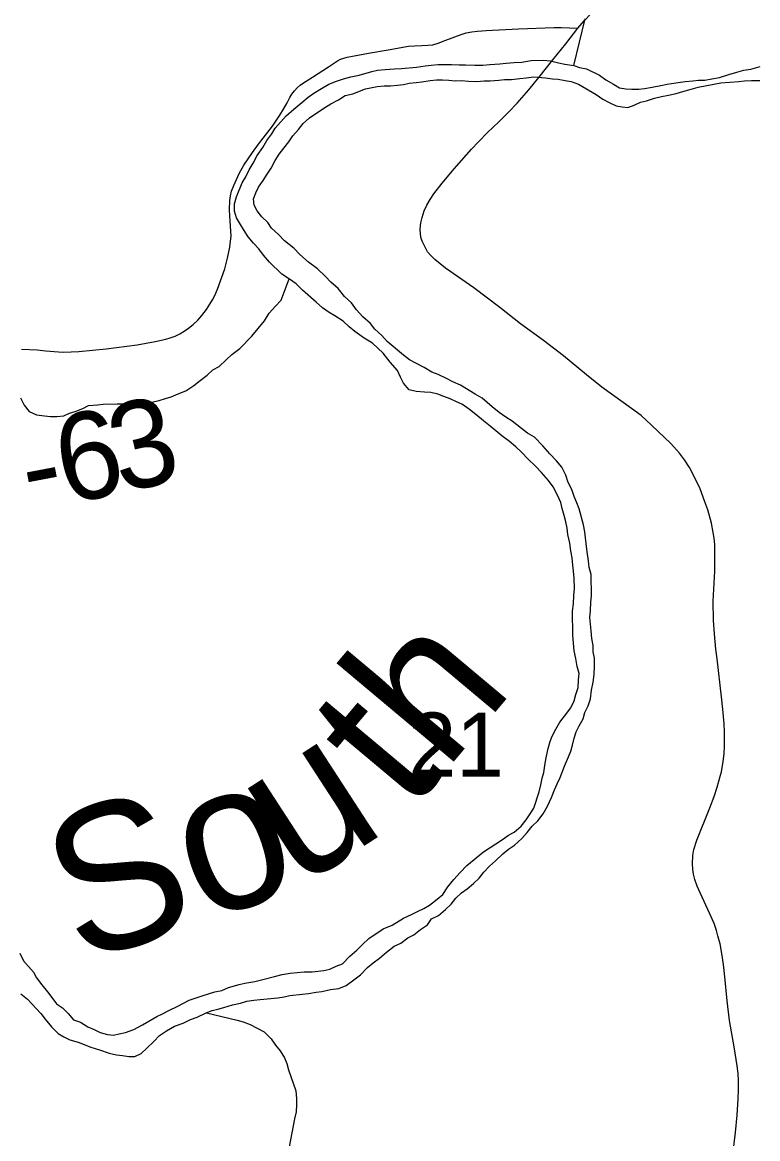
# Model space of a CAD drawing. Extents: x -3.3 to 34, y 0 to 56.8.
# Drawn here: x -2.175 to -1.696, y 29.951 to 30.679 of the extents above; entities that cross this region are included whole.
import ezdxf

# ---------------------------------------------------------------- set-up
doc = ezdxf.new("R2010")
doc.units = 0
for name, color, linetype in [('GM_X_Major_River', 7, 'Continuous'), ('GM_X_Major_River_Text', 7, 'Continuous'), ('GM_X_Section_Text', 7, 'Continuous'), ('GM_X_State_Route', 7, 'Continuous'), ('GM_X_Township_Road', 7, 'Continuous'), ('GM_X_Township_Road_Text', 7, 'Continuous'), ('GT_Project_Soil_Layers', 7, 'Continuous')]:
    doc.layers.add(name, color=color, linetype=linetype)

msp = doc.modelspace()

# ---------------------------------------------------------------- linework, layer by layer
at = {"layer": 'GM_X_Major_River'}
for points in [[(-2.03157, 30.57411), (-2.02934, 30.57794), (-2.02713, 30.58252), (-2.02453, 30.58674), (-2.02195, 30.59171), (-2.01823, 30.59707), (-2.01563, 30.60166), (-2.01228, 30.60588), (-2.01006, 30.6097), (-2.00296, 30.61777), (-1.99809, 30.62202), (-1.99284, 30.62626), (-1.98871, 30.62973), (-1.98496, 30.63244), (-1.98007, 30.63555), (-1.97518, 30.63827), (-1.97027, 30.64024), (-1.96574, 30.64182), (-1.96083, 30.64302), (-1.95554, 30.64424), (-1.94723, 30.64663), (-1.94345, 30.64744), (-1.93852, 30.64789), (-1.93246, 30.64835), (-1.92792, 30.64842), (-1.91807, 30.64931), (-1.91239, 30.65015), (-1.9086, 30.65058), (-1.90406, 30.65103), (-1.89534, 30.65114), (-1.89041, 30.65084), (-1.88624, 30.65089), (-1.88017, 30.6506), (-1.87486, 30.65067), (-1.87032, 30.65111), (-1.86388, 30.65158), (-1.85971, 30.65202), (-1.85441, 30.65247), (-1.84948, 30.65254), (-1.84343, 30.65377), (-1.83547, 30.65388), (-1.83091, 30.65356), (-1.82558, 30.65212), (-1.8214, 30.65142), (-1.8157, 30.65036), (-1.81189, 30.64927), (-1.80733, 30.6482), (-1.79893, 30.64414), (-1.79472, 30.64116), (-1.78975, 30.6382), (-1.78593, 30.63597), (-1.78175, 30.63527), (-1.77795, 30.63495), (-1.77341, 30.63501), (-1.76962, 30.63544), (-1.7647, 30.63627), (-1.75903, 30.63749), (-1.75487, 30.6383), (-1.74919, 30.63914), (-1.74314, 30.63998), (-1.73821, 30.64043), (-1.73443, 30.64087), (-1.73026, 30.64092), (-1.72572, 30.64175), (-1.7208, 30.64257), (-1.71476, 30.64456), (-1.70947, 30.64615), (-1.70494, 30.64735), (-1.7004, 30.64817), (-1.69435, 30.64978)], [(-1.99416, 30.5272), (-1.998, 30.53132), (-2.00413, 30.53617), (-2.00798, 30.54029), (-2.01259, 30.5444), (-2.01492, 30.54816), (-2.01875, 30.5519), (-2.02184, 30.55565), (-2.02379, 30.55942), (-2.02422, 30.56359), (-2.02276, 30.56741), (-2.02091, 30.57123), (-2.01793, 30.57544), (-2.01534, 30.57965), (-2.01274, 30.58348), (-2.01015, 30.58845), (-2.00755, 30.59266), (-2.00457, 30.5965), (-2.00121, 30.60072), (-1.99861, 30.60455), (-1.99487, 30.60878), (-1.99189, 30.61261), (-1.98777, 30.61647), (-1.97838, 30.62267), (-1.97386, 30.62539), (-1.96897, 30.62811), (-1.96446, 30.63083), (-1.95955, 30.63204), (-1.95125, 30.63519), (-1.94368, 30.63681), (-1.93914, 30.63725), (-1.93497, 30.63731), (-1.93042, 30.63775), (-1.92664, 30.63819), (-1.92286, 30.639), (-1.91831, 30.63944), (-1.91453, 30.63987), (-1.90923, 30.64071), (-1.90507, 30.64114), (-1.90127, 30.6412), (-1.8971, 30.64087), (-1.89292, 30.64055), (-1.88875, 30.64061), (-1.8842, 30.6403), (-1.87889, 30.63999), (-1.87396, 30.64044), (-1.87017, 30.64049), (-1.86449, 30.64095), (-1.8607, 30.64138), (-1.85615, 30.64145), (-1.85085, 30.6419), (-1.84669, 30.64234), (-1.84177, 30.64316), (-1.83418, 30.64251), (-1.82962, 30.64181), (-1.82582, 30.64149), (-1.82126, 30.64079), (-1.81746, 30.64009), (-1.81251, 30.63826), (-1.80104, 30.63159), (-1.79683, 30.62861), (-1.79263, 30.62639), (-1.78805, 30.62418), (-1.78425, 30.62347), (-1.78045, 30.62314), (-1.7763, 30.62472), (-1.77216, 30.62668), (-1.76838, 30.62749), (-1.76309, 30.62908), (-1.75855, 30.63028), (-1.75402, 30.6311), (-1.7491, 30.63231), (-1.74457, 30.63351), (-1.74079, 30.63471), (-1.73475, 30.63631), (-1.72454, 30.63835), (-1.72, 30.63917), (-1.70825, 30.64009), (-1.70447, 30.64053), (-1.69992, 30.64059), (-1.69461, 30.64066)], [(-1.88527, 30.12912), (-1.8744, 30.138), (-1.86199, 30.14614), (-1.85824, 30.14885), (-1.85447, 30.1508), (-1.84997, 30.15466), (-1.84662, 30.15888), (-1.84402, 30.16271), (-1.84179, 30.16654), (-1.83814, 30.17721), (-1.83707, 30.18178), (-1.83637, 30.18596), (-1.83528, 30.18977), (-1.83423, 30.19586), (-1.83353, 30.20042), (-1.83246, 30.20537), (-1.83137, 30.20918), (-1.82991, 30.213), (-1.82732, 30.21796), (-1.82472, 30.22256), (-1.82174, 30.22639), (-1.81764, 30.23176), (-1.81543, 30.23635), (-1.81435, 30.24053), (-1.8129, 30.24511), (-1.81258, 30.25004), (-1.81226, 30.25422), (-1.81346, 30.25876), (-1.81429, 30.26406), (-1.81549, 30.26898), (-1.81639, 30.27921), (-1.8166, 30.29477), (-1.81591, 30.29971), (-1.8156, 30.30503), (-1.81528, 30.30958), (-1.81537, 30.31642), (-1.81581, 30.32096), (-1.81624, 30.32475), (-1.81669, 30.32968), (-1.81751, 30.33422), (-1.81833, 30.33914), (-1.81955, 30.34482), (-1.81998, 30.34899), (-1.8208, 30.35315), (-1.82199, 30.35731), (-1.82319, 30.36184), (-1.824, 30.36563), (-1.82634, 30.37053), (-1.82906, 30.3758), (-1.83216, 30.37993), (-1.83677, 30.38518), (-1.84062, 30.3893), (-1.84562, 30.39417), (-1.84947, 30.39829), (-1.85331, 30.40203), (-1.85752, 30.40539), (-1.8625, 30.40911), (-1.86634, 30.41247), (-1.87017, 30.41546), (-1.87439, 30.41881), (-1.87937, 30.42292), (-1.88359, 30.42627), (-1.88819, 30.42962), (-1.89238, 30.43146), (-1.8962, 30.43331), (-1.90039, 30.43477), (-1.9042, 30.43623), (-1.90876, 30.43731), (-1.91294, 30.43763), (-1.91825, 30.43793), (-1.92282, 30.43901), (-1.92667, 30.44351), (-1.92862, 30.44728), (-1.93057, 30.4518), (-1.93519, 30.45705), (-1.93983, 30.46306), (-1.94674, 30.46942), (-1.95209, 30.47276), (-1.95822, 30.47722), (-1.96205, 30.48021), (-1.96589, 30.48395), (-1.97125, 30.48729), (-1.97507, 30.48951), (-1.97928, 30.49249), (-1.9835, 30.49623), (-1.99233, 30.50407), (-1.99655, 30.50819), (-2.00076, 30.51117), (-2.00574, 30.51451), (-2.01381, 30.52237), (-2.01766, 30.52687), (-2.02075, 30.531), (-2.02421, 30.53475), (-2.02768, 30.53888), (-2.03039, 30.54301), (-2.03272, 30.54678), (-2.03543, 30.55129), (-2.03663, 30.55545), (-2.03669, 30.56038), (-2.03524, 30.56496), (-2.03157, 30.57411)], [(-1.91543, 30.08735), (-1.91092, 30.09044), (-1.90832, 30.09427), (-1.9038, 30.09661), (-1.8993, 30.10047), (-1.89555, 30.10394), (-1.89257, 30.10777), (-1.88883, 30.11124), (-1.88507, 30.11395), (-1.88095, 30.11742), (-1.8772, 30.12089), (-1.87422, 30.12472), (-1.87048, 30.12857), (-1.86673, 30.13204), (-1.86187, 30.13666), (-1.85812, 30.13975), (-1.85436, 30.14246), (-1.84949, 30.1467), (-1.84613, 30.15054), (-1.84277, 30.15476), (-1.83903, 30.15823), (-1.83568, 30.16282), (-1.83271, 30.1678), (-1.83013, 30.17353), (-1.8283, 30.17849), (-1.82646, 30.18231), (-1.82462, 30.18651), (-1.82168, 30.19376), (-1.81911, 30.19986), (-1.81765, 30.20368), (-1.81656, 30.20749), (-1.81548, 30.21206), (-1.81402, 30.21625), (-1.81218, 30.22007), (-1.80959, 30.22466), (-1.8085, 30.22885), (-1.80629, 30.23306), (-1.80483, 30.23763), (-1.80415, 30.24333), (-1.80309, 30.24866), (-1.80239, 30.2536), (-1.80209, 30.25892), (-1.80216, 30.26423), (-1.80297, 30.26839), (-1.80303, 30.27257), (-1.80385, 30.27711), (-1.80429, 30.28204), (-1.80517, 30.29075), (-1.80485, 30.29531), (-1.80454, 30.30063), (-1.80422, 30.30481), (-1.80441, 30.31884), (-1.80561, 30.32338), (-1.80604, 30.32755), (-1.80688, 30.33361), (-1.80771, 30.33891), (-1.80814, 30.3427), (-1.80857, 30.34649), (-1.80939, 30.35103), (-1.81219, 30.36162), (-1.81376, 30.36539), (-1.81533, 30.36954), (-1.81691, 30.37407), (-1.81924, 30.3786), (-1.82083, 30.38351), (-1.82355, 30.38878), (-1.82702, 30.39291), (-1.83125, 30.3974), (-1.83587, 30.40265), (-1.84126, 30.40827), (-1.84584, 30.41086), (-1.84967, 30.41384), (-1.85581, 30.41869), (-1.86001, 30.42129), (-1.86422, 30.42427), (-1.86882, 30.428), (-1.87535, 30.4336), (-1.87993, 30.43619), (-1.88949, 30.44213), (-1.89445, 30.44434), (-1.89865, 30.44656), (-1.90399, 30.44914), (-1.90819, 30.4506), (-1.91316, 30.45357), (-1.9185, 30.45653), (-1.9227, 30.45875), (-1.92654, 30.46173), (-1.93727, 30.47069), (-1.94074, 30.47443), (-1.94534, 30.47854), (-1.94805, 30.4823), (-1.95304, 30.48678), (-1.95727, 30.49128), (-1.96036, 30.49579), (-1.96497, 30.4999), (-1.96921, 30.50515), (-1.97382, 30.50926), (-1.97728, 30.51301), (-1.98265, 30.51787), (-1.9884, 30.52235), (-1.99416, 30.5272)], [(-2.17648, 30.07197), (-2.17414, 30.06707), (-2.17067, 30.06333), (-2.16759, 30.05957), (-2.16564, 30.05581), (-2.16217, 30.0513), (-2.15832, 30.0468), (-2.15561, 30.04304), (-2.15252, 30.03891), (-2.1487, 30.03631), (-2.14485, 30.03257), (-2.14139, 30.02844), (-2.13682, 30.02699), (-2.13223, 30.02401), (-2.12803, 30.02217), (-2.12421, 30.02033), (-2.11926, 30.01888), (-2.11547, 30.01855), (-2.11169, 30.01937), (-2.10753, 30.02018), (-2.10224, 30.02215), (-2.0966, 30.02527), (-2.09246, 30.0276), (-2.08719, 30.03071), (-2.08305, 30.03266), (-2.07928, 30.03461), (-2.07363, 30.03735), (-2.0661, 30.04125), (-2.06157, 30.04282), (-2.05704, 30.0444), (-2.04949, 30.04678), (-2.04495, 30.04761), (-2.04043, 30.04957), (-2.03363, 30.05156), (-2.02985, 30.05237), (-2.02342, 30.0536), (-2.01813, 30.05481), (-2.01057, 30.05681), (-2.00566, 30.05802), (-2.00036, 30.05885), (-1.99127, 30.05973), (-1.98596, 30.05981), (-1.97839, 30.06067), (-1.97461, 30.06148), (-1.97047, 30.06344), (-1.96631, 30.06501), (-1.96145, 30.07001), (-1.95695, 30.07387), (-1.95322, 30.07771), (-1.9491, 30.08157), (-1.9397, 30.08777), (-1.93404, 30.09012), (-1.92652, 30.09478), (-1.92125, 30.09713), (-1.91748, 30.09908), (-1.91334, 30.10103), (-1.90957, 30.10336), (-1.9047, 30.10723), (-1.90095, 30.11031), (-1.8976, 30.11529), (-1.89387, 30.1199), (-1.88976, 30.12451), (-1.88527, 30.12912)], [(-2.17574, 30.04542), (-2.17152, 30.04207), (-2.16268, 30.0327), (-2.15997, 30.02895), (-2.15574, 30.02407), (-2.1515, 30.01957), (-2.14768, 30.01735), (-2.14387, 30.0155), (-2.13854, 30.01406), (-2.13015, 30.01076), (-2.12444, 30.00894), (-2.11834, 30.00675), (-2.1134, 30.00568), (-2.1096, 30.00535), (-2.10542, 30.00465), (-2.10163, 30.00471), (-2.09749, 30.00666), (-2.09374, 30.01013), (-2.08925, 30.01436), (-2.08551, 30.01821), (-2.081, 30.02131), (-2.07573, 30.02442), (-2.07007, 30.02639), (-2.06517, 30.02873), (-2.06102, 30.03031), (-2.05499, 30.03305), (-2.05122, 30.03462), (-2.04744, 30.03543), (-2.04367, 30.03662), (-2.038, 30.03822), (-2.03271, 30.03943), (-2.02855, 30.04062), (-2.02402, 30.04145), (-2.01985, 30.04188), (-2.00849, 30.0428), (-2.00433, 30.04361), (-2.00055, 30.04443), (-1.99259, 30.0453), (-1.98843, 30.04573), (-1.98351, 30.04656), (-1.97972, 30.04699), (-1.97405, 30.04821), (-1.96876, 30.04904), (-1.96385, 30.051), (-1.95897, 30.05449), (-1.95447, 30.05796), (-1.94998, 30.06258), (-1.94623, 30.06567), (-1.9421, 30.06876), (-1.9376, 30.07262), (-1.93272, 30.07648), (-1.9282, 30.07844), (-1.9237, 30.08192), (-1.91993, 30.08387), (-1.91543, 30.08735)]]:
    msp.add_lwpolyline(points, dxfattribs=at)
at = {"layer": 'GM_X_State_Route'}
for points in [[(-1.86455, 30.6138), (-1.85796, 30.62017), (-1.85255, 30.62595), (-1.84503, 30.63452), (-1.83854, 30.64272), (-1.82937, 30.65408), (-1.82094, 30.66461), (-1.81293, 30.67478), (-1.80866, 30.67987), (-1.80454, 30.68415), (-1.80044, 30.68785), (-1.79674, 30.69048), (-1.79328, 30.69237), (-1.78745, 30.69483), (-1.78219, 30.6964), (-1.77758, 30.69722), (-1.77306, 30.69755), (-1.76895, 30.69747), (-1.76443, 30.69697), (-1.75933, 30.69607), (-1.75272, 30.69473), (-1.75175, 30.69454)], [(-1.71182, 29.9426), (-1.71042, 29.9551), (-1.70938, 29.96641), (-1.70862, 29.97713), (-1.70837, 29.98264), (-1.70845, 29.98872), (-1.7087, 29.99365), (-1.70936, 29.99858), (-1.71133, 30.01099), (-1.7142, 30.02818), (-1.71577, 30.04091), (-1.71733, 30.05645), (-1.71824, 30.06467), (-1.71922, 30.07183), (-1.72045, 30.07807), (-1.72177, 30.08333), (-1.72275, 30.08678), (-1.72432, 30.09123), (-1.7272, 30.09796), (-1.73319, 30.11087), (-1.73525, 30.11564), (-1.73681, 30.12008), (-1.73772, 30.12353), (-1.73821, 30.12665), (-1.73845, 30.13019), (-1.73821, 30.13561), (-1.73747, 30.13948), (-1.73564, 30.14552), (-1.72703, 30.16673), (-1.72421, 30.17417), (-1.72226, 30.18016), (-1.72006, 30.18787), (-1.71958, 30.1901), (-1.71842, 30.19685), (-1.71783, 30.20195), (-1.7175, 30.20707), (-1.71742, 30.21101), (-1.7175, 30.21625), (-1.71766, 30.22151), (-1.71856, 30.23105), (-1.71947, 30.23903), (-1.72234, 30.26377), (-1.72308, 30.27001), (-1.72399, 30.28004), (-1.72473, 30.28867), (-1.72498, 30.30142), (-1.72391, 30.32098), (-1.72374, 30.3278), (-1.72391, 30.33824), (-1.72432, 30.34243), (-1.72489, 30.34613), (-1.72604, 30.3523), (-1.72843, 30.36093), (-1.73023, 30.36619), (-1.73344, 30.37458), (-1.73706, 30.38222), (-1.74034, 30.38838), (-1.74355, 30.39348), (-1.74676, 30.39775), (-1.75245, 30.40422), (-1.76504, 30.41617), (-1.7718, 30.42235), (-1.77816, 30.42702), (-1.79742, 30.44077), (-1.80746, 30.44886), (-1.82235, 30.46133), (-1.83547, 30.47122), (-1.85035, 30.48212), (-1.8639, 30.4927), (-1.88084, 30.50553), (-1.89925, 30.51849), (-1.90606, 30.52402), (-1.90885, 30.52664), (-1.91092, 30.52911), (-1.91256, 30.53199), (-1.91428, 30.53561), (-1.91511, 30.53783), (-1.9156, 30.54063), (-1.91568, 30.54391), (-1.91518, 30.54785), (-1.91445, 30.55147), (-1.91314, 30.55576), (-1.91136, 30.55955), (-1.90918, 30.56322), (-1.90673, 30.56683), (-1.9013, 30.57383), (-1.89349, 30.58304), (-1.88223, 30.59603), (-1.87762, 30.60079), (-1.87187, 30.60671), (-1.86455, 30.6138)]]:
    msp.add_lwpolyline(points, dxfattribs=at)
at = {"layer": 'GM_X_Township_Road'}
msp.add_lwpolyline([(-2.17538, 30.46561), (-2.16517, 30.46515), (-2.15957, 30.46461), (-2.15116, 30.4638), (-2.14791, 30.46362), (-2.13806, 30.46398), (-2.12019, 30.46585), (-2.10002, 30.4685), (-2.08836, 30.47049), (-2.08144, 30.47204), (-2.07847, 30.47294), (-2.07531, 30.47416), (-2.07225, 30.47563), (-2.06932, 30.47734), (-2.06654, 30.47928), (-2.06357, 30.4817), (-2.06054, 30.48451), (-2.058, 30.48747), (-2.05493, 30.49136), (-2.05267, 30.49489), (-2.05105, 30.49769), (-2.04942, 30.50049), (-2.04761, 30.50464), (-2.043, 30.51793), (-2.04119, 30.52497), (-2.03975, 30.53211), (-2.0392, 30.53591), (-2.03884, 30.53932), (-2.03966, 30.55254), (-2.0399, 30.55633), (-2.03976, 30.56247), (-2.03929, 30.56551), (-2.03855, 30.56849), (-2.03715, 30.57235), (-2.03361, 30.58001), (-2.03056, 30.58555), (-2.02484, 30.59383), (-2.02102, 30.59927), (-2.01192, 30.61091), (-2.00962, 30.61416), (-2.0071, 30.61811), (-2.00468, 30.62211), (-2.00235, 30.62617), (-2.00056, 30.62955), (-1.99922, 30.6318), (-1.99765, 30.63389), (-1.99587, 30.63582), (-1.9939, 30.63755), (-1.99176, 30.63907), (-1.9858, 30.64294), (-1.9755, 30.64963), (-1.96961, 30.65345), (-1.96763, 30.65452), (-1.96553, 30.65535), (-1.96335, 30.65592), (-1.9493, 30.65844), (-1.93658, 30.66067), (-1.92337, 30.66298), (-1.91938, 30.66335), (-1.9146, 30.66359), (-1.91071, 30.66368), (-1.90746, 30.66404), (-1.90394, 30.66495), (-1.89897, 30.66693), (-1.88894, 30.67073), (-1.88568, 30.67172), (-1.88198, 30.67245), (-1.87831, 30.67292), (-1.87267, 30.67335), (-1.85162, 30.67429), (-1.82848, 30.67534), (-1.82379, 30.67525), (-1.81293, 30.67478)], dxfattribs=at)
at = {"layer": 'GT_Project_Soil_Layers'}
for points in [[(-1.80853, 30.68082), (-1.81577, 30.65037)], [(-2.17605, 30.43399), (-2.1737, 30.42908), (-2.17024, 30.42496), (-2.16565, 30.42275), (-2.16034, 30.42206), (-2.15654, 30.42173), (-2.15237, 30.42179), (-2.14783, 30.42223), (-2.14406, 30.4238), (-2.14028, 30.42499), (-2.13538, 30.42696), (-2.13161, 30.42891), (-2.12593, 30.42936), (-2.12214, 30.4298), (-2.11305, 30.42992), (-2.10888, 30.42998), (-2.09485, 30.43017), (-2.09069, 30.43099), (-2.08577, 30.4322), (-2.08162, 30.43339), (-2.07784, 30.43458), (-2.07332, 30.43654), (-2.06842, 30.43851), (-2.06316, 30.442), (-2.05903, 30.44509), (-2.05452, 30.44857), (-2.05078, 30.45203), (-2.04664, 30.45437), (-2.04215, 30.45861), (-2.0384, 30.46207), (-2.03314, 30.46594), (-2.02529, 30.47402), (-2.01708, 30.484), (-2.01412, 30.48897), (-2.01001, 30.49358), (-2.00627, 30.49743), (-2.00102, 30.51134)], [(-2.05487, 30.0331), (-2.03483, 30.02839), (-2.03103, 30.02731), (-2.02645, 30.02547), (-2.01729, 30.02067), (-2.01268, 30.01618), (-2.00997, 30.01204), (-2.00688, 30.00829), (-2.00417, 30.00377), (-2.0026, 30), (-2.00141, 29.99584), (-1.99667, 29.98225), (-1.99623, 29.97732), (-1.99617, 29.97315), (-1.99649, 29.96859), (-1.99757, 29.96402), (-2.00181, 29.9412)]]:
    msp.add_lwpolyline(points, dxfattribs=at)

# ---------------------------------------------------------------- texts
at = {"layer": 'GM_X_Major_River_Text'}
for s, height, rotation, p in [('th', 0.09469, 49.99287, (-1.92209, 30.16311)), ('u', 0.09469, 32.99435, (-1.99524, 30.11387)), ('So', 0.094695, 18.99582, (-2.13769, 30.06455))]:
    msp.add_text(s, height=height, rotation=rotation, dxfattribs=at).set_placement(p)
at = {"layer": 'GM_X_Section_Text'}
msp.add_text('21', height=0.041856, rotation=0.00001, dxfattribs=at).set_placement((-1.92339, 30.18692))
at = {"layer": 'GM_X_Township_Road_Text'}
for s, rotation, p in [('3', 13.12648, (-2.11065, 30.37163)), ('6', 11.22344, (-2.147, 30.36438)), ('-', 10.71672, (-2.17046, 30.35994))]:
    msp.add_text(s, height=0.05682, rotation=rotation, dxfattribs=at).set_placement(p)

doc.saveas('drawing.dxf')
